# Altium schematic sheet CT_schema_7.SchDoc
size 369 x 245 mm
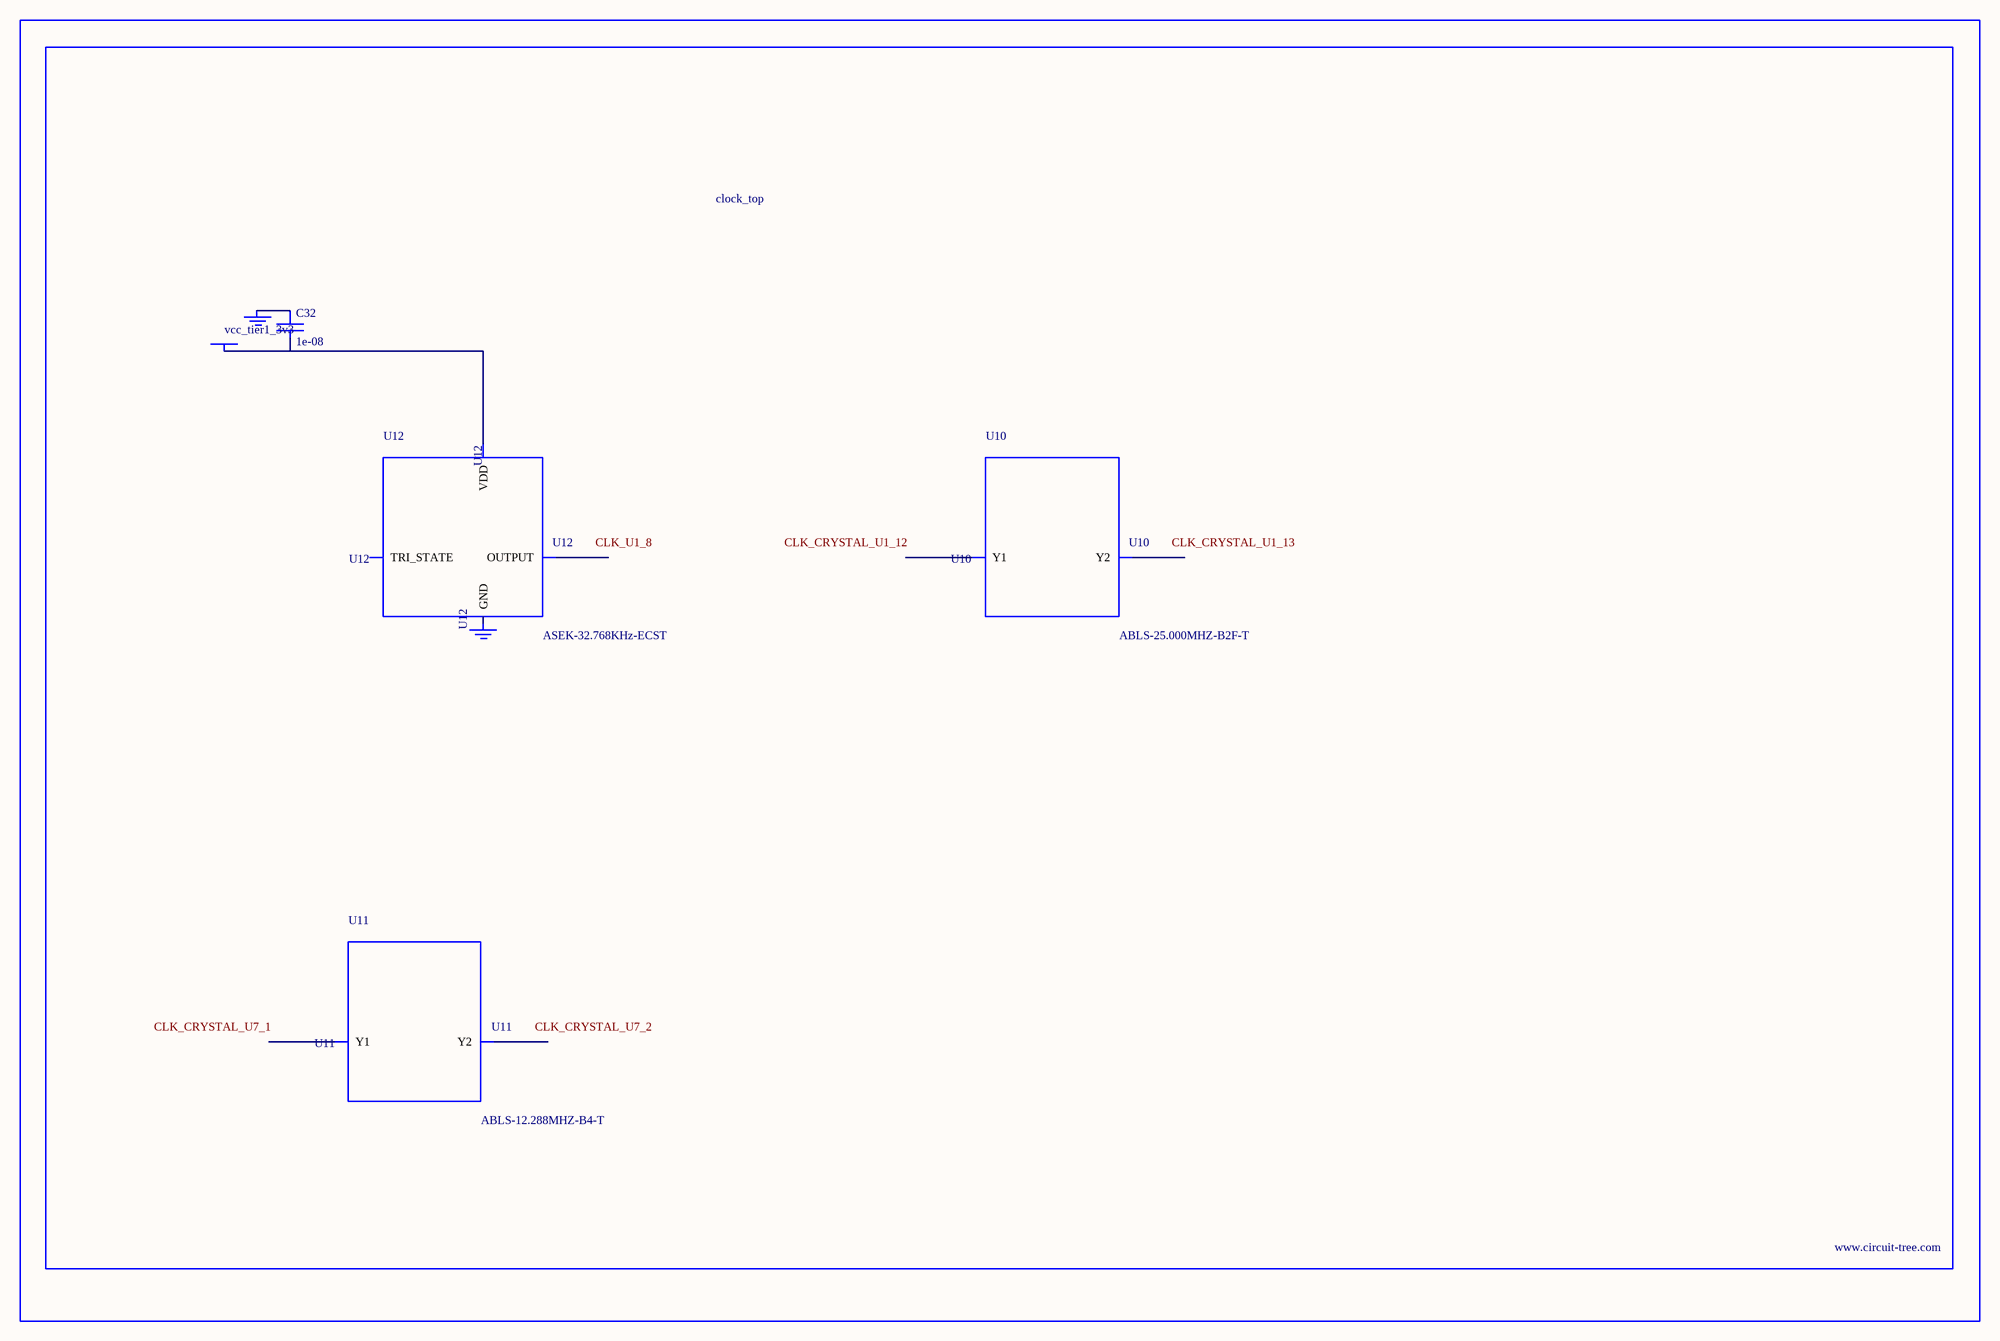
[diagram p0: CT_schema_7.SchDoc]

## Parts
BORDER6  (no value)
C32  1e-08  [C0402]
GND_INSTANCE_6_0  (no value)
GND_INSTANCE_6_1  (no value)
POWER_INSTANCE_6_0  vcc_tier1_3v3
U10  ABLS-25.000MHZ-B2F-T  [ABLS-25.000MHZ-B2F-T]
U11  ABLS-12.288MHZ-B4-T  [ABLS-12.288MHZ-B4-T]
U12  ASEK-32.768KHz-ECST  [ASEK]

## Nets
NetC32_1: C32.1 GND_INSTANCE_6_0.0(GND)
NetC32_2: C32.2 POWER_INSTANCE_6_0.0(PWR) U12.4(VDD)

Not connected (* = marked no-connect by the designer): GND_INSTANCE_6_1 0(GND); U10 1(Y1) 2(Y2); U11 1(Y1) 2(Y2); U12 1(TRI_STATE) 2(GND) 3(OUTPUT)

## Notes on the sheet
- Labels drawn without touching a wire or pin: CLK_CRYSTAL_U1_12, CLK_CRYSTAL_U1_13, CLK_CRYSTAL_U7_1, CLK_CRYSTAL_U7_2, CLK_U1_8

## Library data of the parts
BORDER6 = BORDER_PAGE6
C32 = C0402C103K3RAC
GND_INSTANCE_6_0 GND_INSTANCE_6_1 = GND
POWER_INSTANCE_6_0 = PWR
